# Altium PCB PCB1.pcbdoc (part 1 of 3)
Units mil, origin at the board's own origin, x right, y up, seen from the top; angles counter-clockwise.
Board outline 3256.12 x 1802.31 mil, 4 copper layers (Top Layer, Inner1, Inner2, Bottom Layer); 101 components, 70 nets, 295 pads, 151 vias.
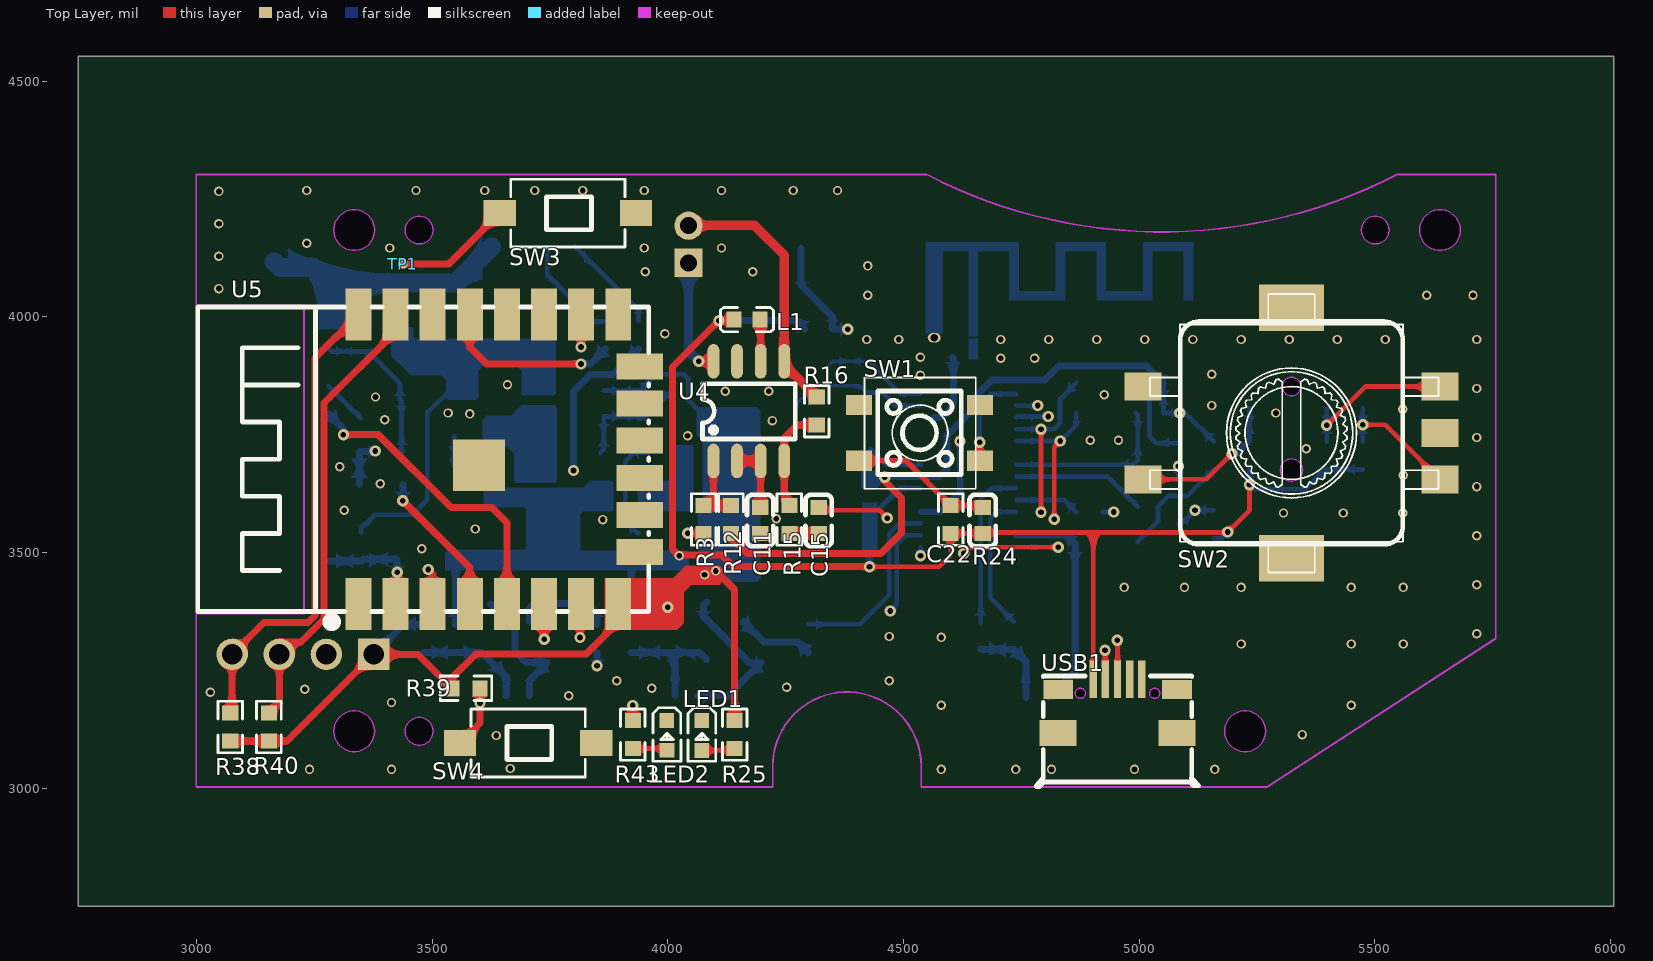
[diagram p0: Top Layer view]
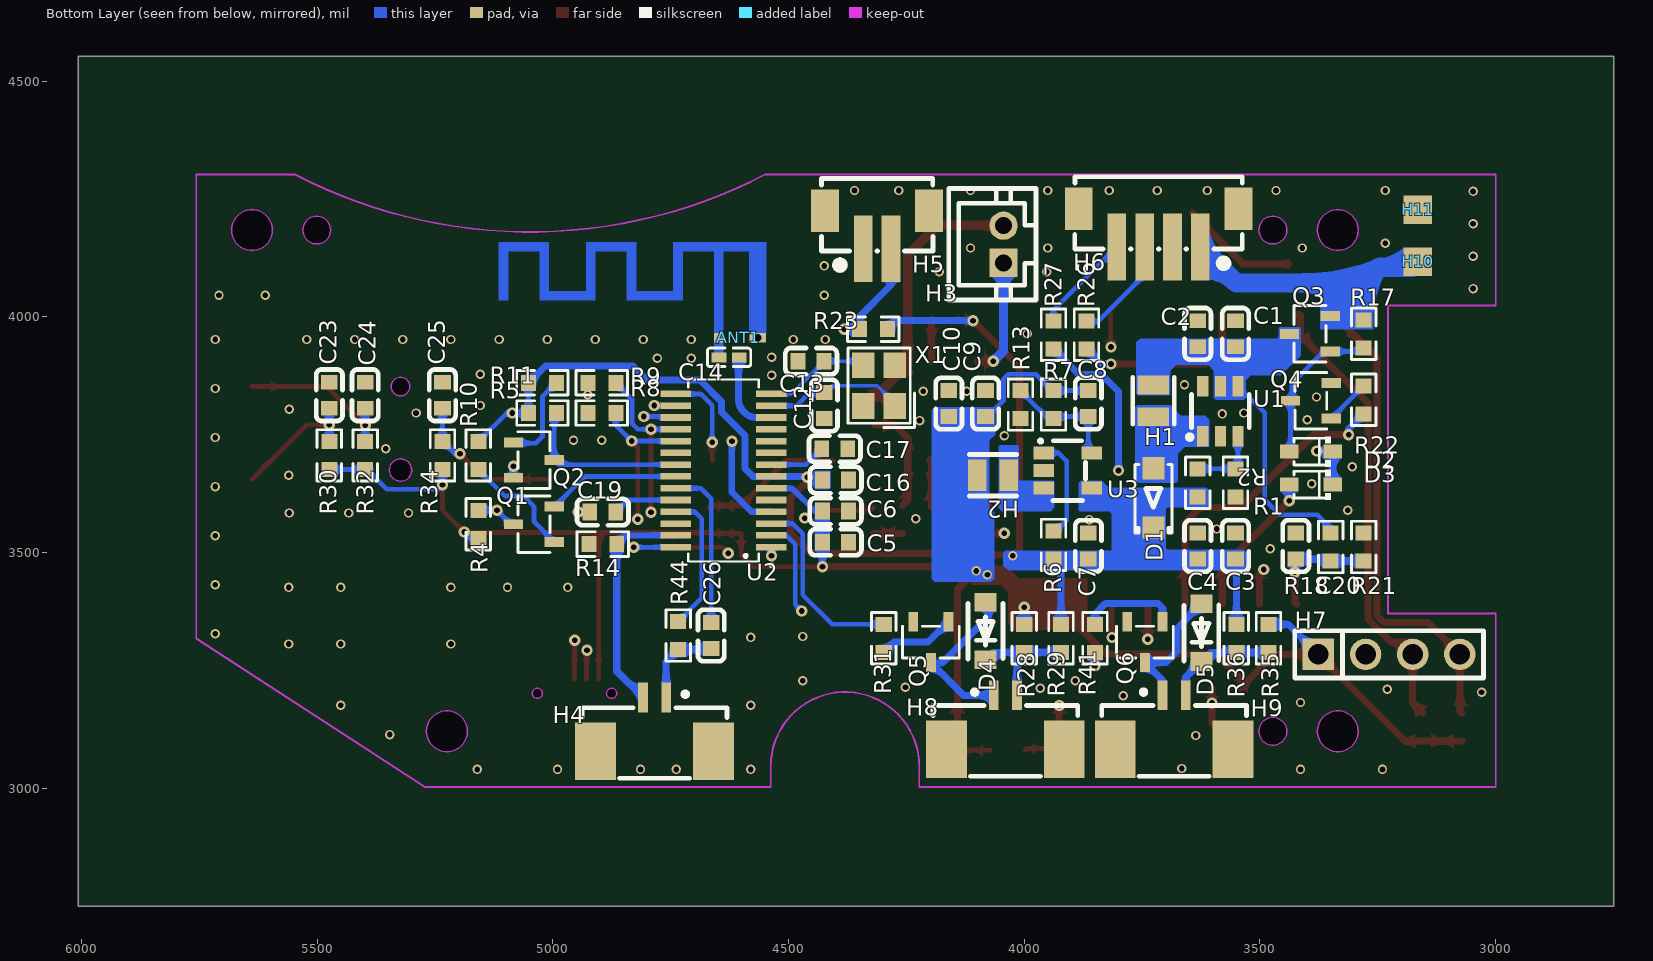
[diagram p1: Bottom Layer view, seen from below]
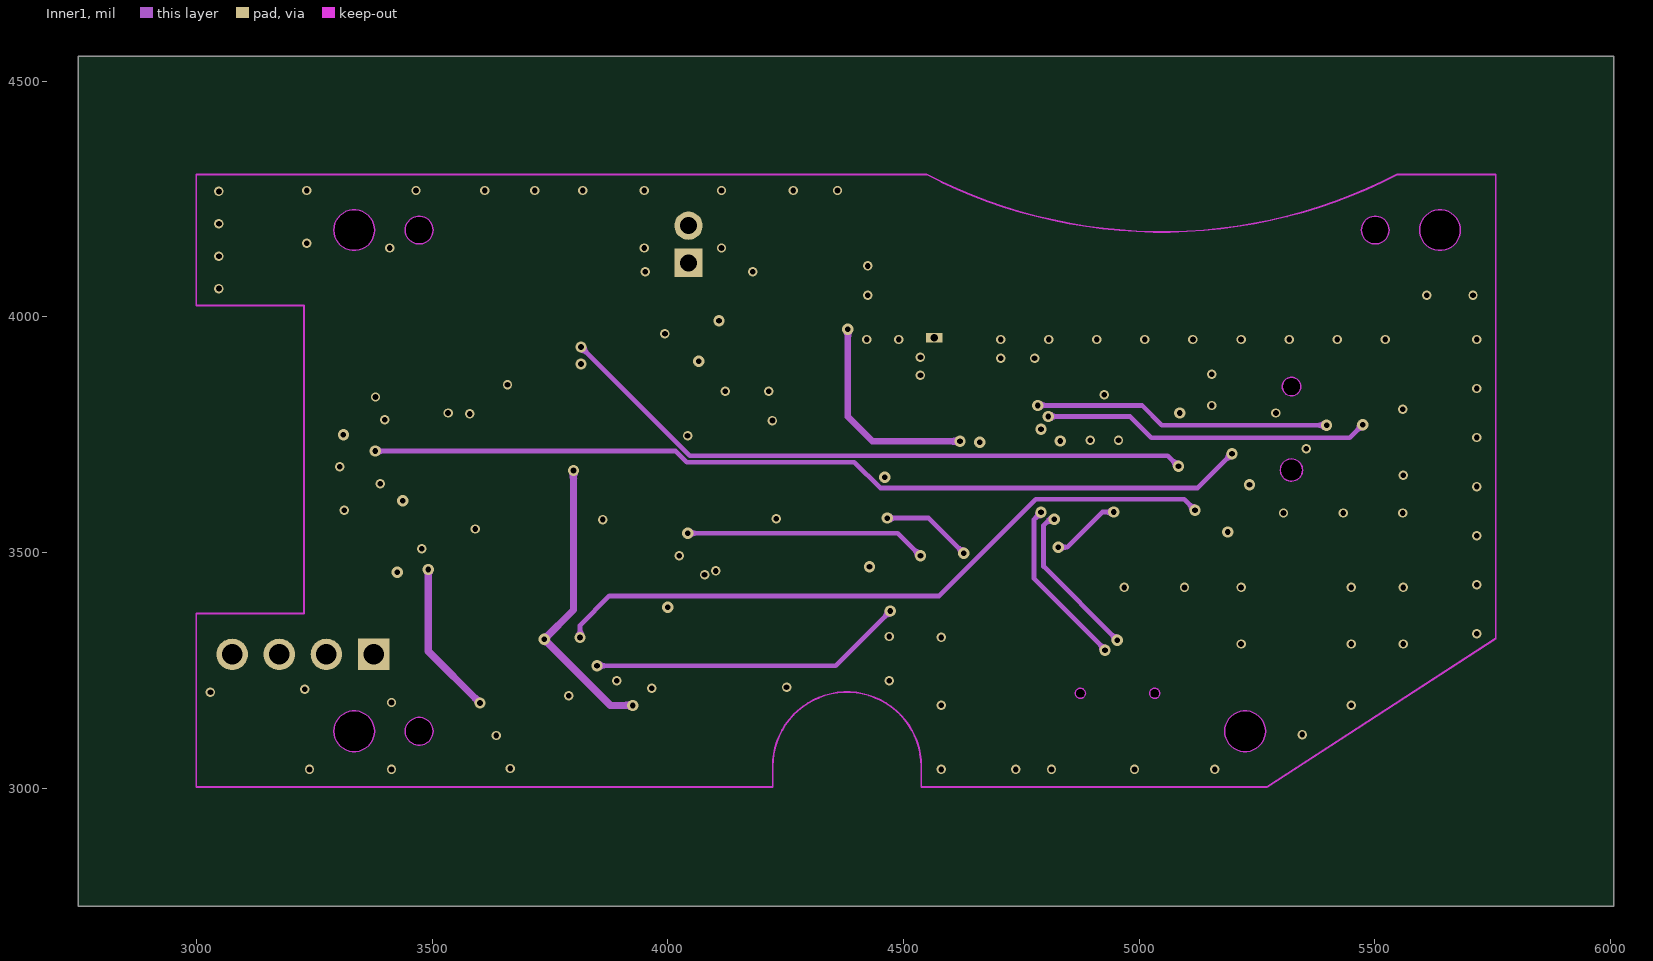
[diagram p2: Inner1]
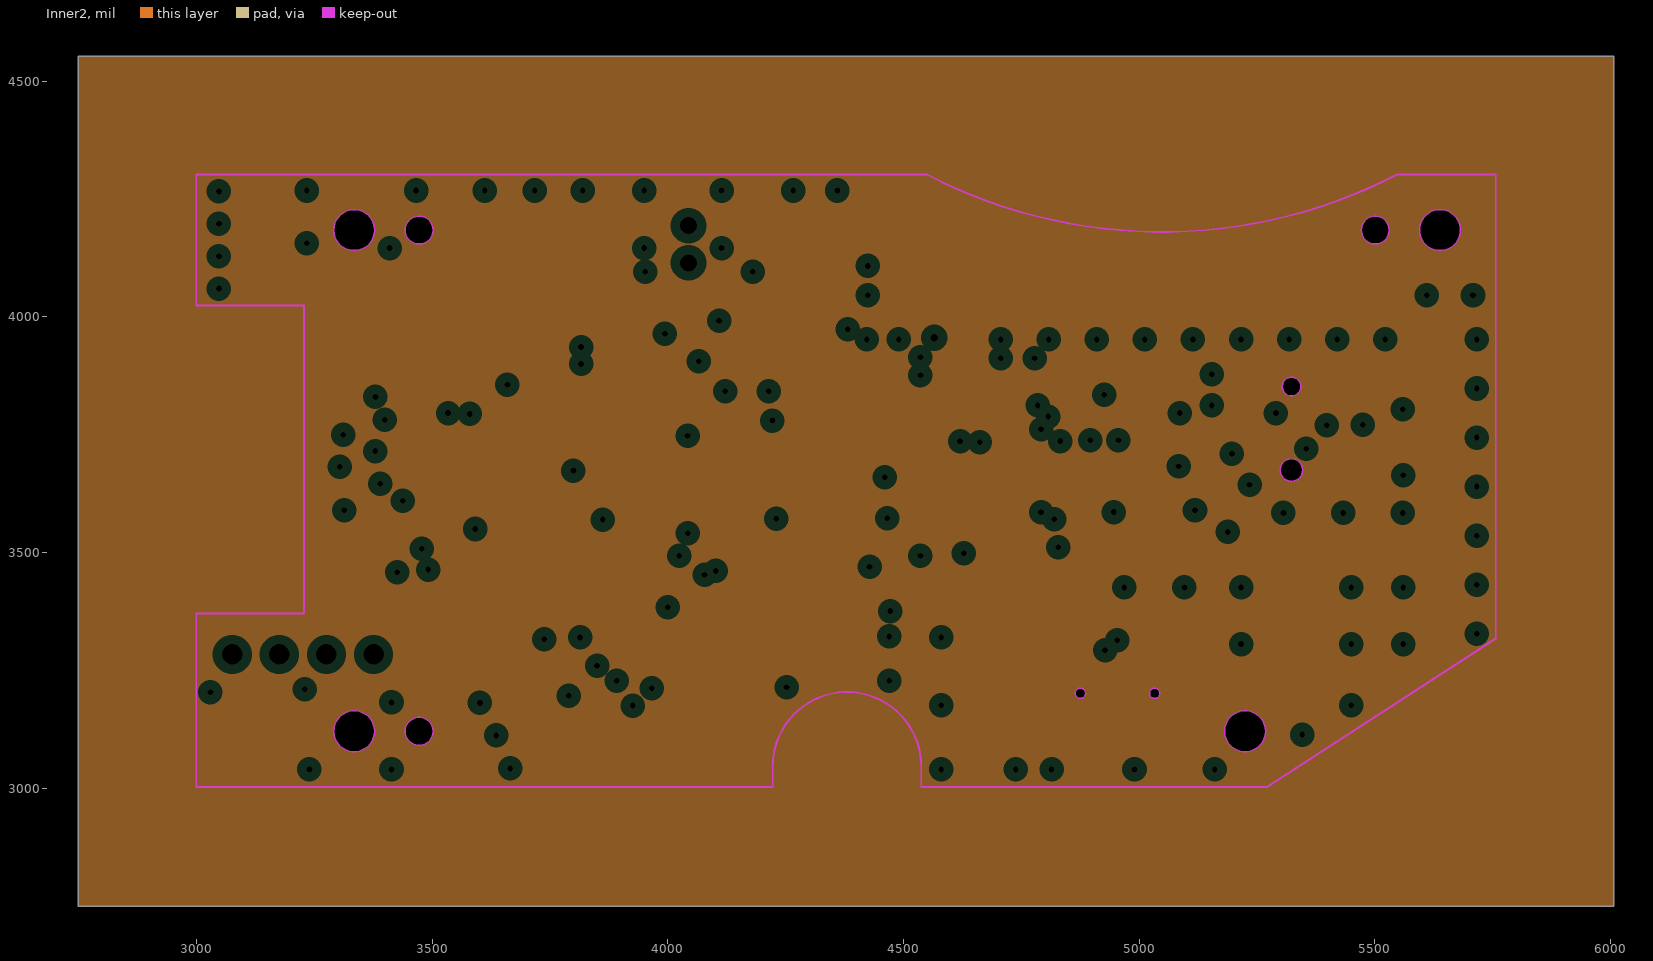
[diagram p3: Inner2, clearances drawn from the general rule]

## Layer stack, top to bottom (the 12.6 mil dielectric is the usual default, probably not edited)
Top Layer: signal copper (thickness not stored)
Dielectric: dielectric 12.6, FR-4, Dk 4.8
Inner1: signal copper (thickness not stored)
Dielectric: dielectric 12.6, FR-4, Dk 4.8
Inner2: plane copper (thickness not stored)
Dielectric: dielectric 12.6, FR-4, Dk 4.8
Bottom Layer: signal copper (thickness not stored)

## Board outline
6006.12,2750 2750,2750 2750,4552.31 6006.12,4552.31
cut-out: 5267.93,3120.93 cw(c5224.62,3120.93) 5181.32,3120.93 cw(c5224.62,3120.93)
cut-out: 5681.32,4183.94 cw(c5638.01,4183.94) 5594.7,4183.94 cw(c5638.01,4183.94)
cut-out: 3378.17,4183.94 cw(c3334.86,4183.94) 3291.55,4183.94 cw(c3334.86,4183.94)
cut-out: 3502.18,3120.93 cw(c3472.66,3120.93) 3443.13,3120.93 cw(c3472.66,3120.93)
cut-out: 3378.17,3120.93 cw(c3334.86,3120.93) 3291.55,3120.93 cw(c3334.86,3120.93)
cut-out: 3443.13,4183.94 cw(c3472.66,4183.94) 3502.18,4183.94 cw(c3472.66,4183.94)
cut-out: 5471.13,4183.94 cw(c5500.66,4183.94) 5530.18,4183.94 cw(c5500.66,4183.94)

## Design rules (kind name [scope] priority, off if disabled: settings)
BoardOutlineClearance copperThickness1oz [All] p0: genericclearance=10 ignorepadtopadclearanceinfootprint=FALSE except(0: Arc-SplitContinuation Track-SplitContinuation SMDPad-SplitContinuation THPad-SplitContinuation Via-SplitContinuation Fill-SplitContinuation Poly-SplitContinuation Region-SplitContinuation Text-SplitContinuation; 6: SMDPad-CutoutEdge THPad-CutoutEdge Via-CutoutEdge Fill-CutoutEdge Region-CutoutEdge; 11.8: Track-OutlineEdge SMDPad-OutlineEdge THPad-OutlineEdge Via-OutlineEdge Fill-OutlineEdge Region-OutlineEdge Poly-OutlineEdge Text-OutlineEdge Track-CutoutEdge)
BoardOutlineClearance copperThickness2oz [All] p0: genericclearance=10 ignorepadtopadclearanceinfootprint=FALSE except(0: Arc-SplitContinuation Track-SplitContinuation SMDPad-SplitContinuation THPad-SplitContinuation Via-SplitContinuation Fill-SplitContinuation Poly-SplitContinuation Region-SplitContinuation Text-SplitContinuation; 6: SMDPad-CutoutEdge THPad-CutoutEdge Via-CutoutEdge Fill-CutoutEdge Region-CutoutEdge; 11.8: Track-OutlineEdge SMDPad-OutlineEdge THPad-OutlineEdge Via-OutlineEdge Fill-OutlineEdge Region-OutlineEdge Poly-OutlineEdge Text-OutlineEdge Track-CutoutEdge)
BoardOutlineClearance copperThicknessInner0.5oz [All] p0: genericclearance=10 ignorepadtopadclearanceinfootprint=FALSE except(0: Arc-SplitContinuation Track-SplitContinuation SMDPad-SplitContinuation THPad-SplitContinuation Via-SplitContinuation Fill-SplitContinuation Poly-SplitContinuation Region-SplitContinuation Text-SplitContinuation; 6: SMDPad-CutoutEdge THPad-CutoutEdge Via-CutoutEdge Fill-CutoutEdge Region-CutoutEdge; 11.8: Track-OutlineEdge SMDPad-OutlineEdge THPad-OutlineEdge Via-OutlineEdge Fill-OutlineEdge Region-OutlineEdge Poly-OutlineEdge Text-OutlineEdge Track-CutoutEdge)
Clearance copperThickness1oz [(InNet('$1N4815') OR InNet('GND') OR InNet('+5V') OR InNet('VCC') OR InNet('$1N2017') OR InNet('VIN') OR InNet('$1N2789') OR InNet('$1N2785') OR InNet('VDDIO') OR InNet('$1N2965') OR InNet('$1N4810') OR InNet('SGND') OR InNet('PC6') OR InNet('$1N5780') OR InNet('$1N6443') OR InNet('DACL') OR InNet('$1N6492') OR InNet('PA0') OR InNet('EC11_A') OR InNet('EC11_B') OR InNet('EC11_D') OR InNet('POWER_ADC') OR InNet('$1N8684') OR InNet('$1N8688') OR InNet('$1N9109') OR InNet('$1N9106') OR InNet('$1N1680') OR InNet('$1N10424') OR InNet('POWER_SW') OR InNet('$1N2005') OR InNet('LOG_TXD') OR InNet('LOG_RXD') OR InNet('$1N6556') OR InNet('$1N8074') OR InNet('$1N8184') OR InNet('$1N5279') OR InNet('PA2') OR InNet('TXD') OR InNet('$1N5314') OR InNet('RXD') OR InNet('PA3') OR InNet('$1N8729') OR InNet('$1N9116') OR InNet('B+') OR InNet('$1N10478') OR InNet('$1N1955') OR InNet('$1N1696') OR InNet('USB_DP') OR InNet('USB_DM') OR InNet('PC7') OR InNet('$1N6373') OR InNet('DACR') OR InNet('$1N6486') OR InNet('SPK-') OR InNet('BOOT') OR InNet('SPK_LED') OR InNet('MUSIC_SW') OR InNet('LED_PWM') OR InNet('MOTOR_PWM') OR InNet('EN') OR InNet('POWER_IO') OR InNet('POWER_LED') OR InNet('$1N10993') OR InNet('$1N10998') OR InNet('PA4') OR InNet('SPK+') OR InNet('KEY_IO') OR InNet('PA1') OR InNet('$1N14735') OR InNet('$1N10634'))] p1: gap=7 ignorepadtopadclearanceinfootprint=FALSE except(4: Track-Track; 6: Track-SMDPad SMDPad-SMDPad Track-THPad SMDPad-THPad THPad-THPad Track-Via SMDPad-Via THPad-Via Via-Via Track-Fill SMDPad-Fill THPad-Fill Via-Fill Fill-Fill SMDPad-Region THPad-Region Via-Region Fill-Region Region-Region Track-Poly SMDPad-Poly THPad-Poly Via-Poly Fill-Poly Poly-Poly Track-Text SMDPad-Text THPad-Text Via-Text Fill-Text Region-Text Poly-Text Text-Text; 6.9: Track-Hole SMDPad-Hole THPad-Hole Via-Hole Fill-Hole Region-Hole Poly-Hole Text-Hole Sheet-Hole; 11.8: Track-Region Region-Poly Track-Sheet SMDPad-Sheet THPad-Sheet Via-Sheet Fill-Sheet Region-Sheet Poly-Sheet Text-Sheet)
Clearance copperThickness2oz [All] p1: gap=7 ignorepadtopadclearanceinfootprint=FALSE except(6: Track-SMDPad SMDPad-SMDPad Track-THPad SMDPad-THPad THPad-THPad Track-Via SMDPad-Via THPad-Via Via-Via Track-Fill SMDPad-Fill THPad-Fill Via-Fill Fill-Fill SMDPad-Region THPad-Region Via-Region Fill-Region Region-Region Track-Poly SMDPad-Poly THPad-Poly Via-Poly Fill-Poly Poly-Poly Track-Text SMDPad-Text THPad-Text Via-Text Fill-Text Region-Text Poly-Text Text-Text; 6.9: Track-Hole SMDPad-Hole THPad-Hole Via-Hole Fill-Hole Region-Hole Poly-Hole Text-Hole Sheet-Hole; 8: Track-Track; 11.8: Track-Region Region-Poly Track-Sheet SMDPad-Sheet THPad-Sheet Via-Sheet Fill-Sheet Region-Sheet Poly-Sheet Text-Sheet)
Clearance copperThicknessInner0.5oz [All] p1: gap=7 ignorepadtopadclearanceinfootprint=FALSE except(3.5: Track-Track; 6: Track-SMDPad SMDPad-SMDPad Track-THPad SMDPad-THPad THPad-THPad Track-Via SMDPad-Via THPad-Via Via-Via Track-Fill SMDPad-Fill THPad-Fill Via-Fill Fill-Fill SMDPad-Region THPad-Region Via-Region Fill-Region Region-Region Track-Poly SMDPad-Poly THPad-Poly Via-Poly Fill-Poly Poly-Poly Track-Text SMDPad-Text THPad-Text Via-Text Fill-Text Region-Text Poly-Text Text-Text; 6.9: Track-Hole SMDPad-Hole THPad-Hole Via-Hole Fill-Hole Region-Hole Poly-Hole Text-Hole Sheet-Hole; 11.8: Track-Region Region-Poly Track-Sheet SMDPad-Sheet THPad-Sheet Via-Sheet Fill-Sheet Region-Sheet Poly-Sheet Text-Sheet)
DiffPairsRouting differentialPair [All] p1: maxuncoupledlength=10 minlimit=5.9843 maxlimit=5.9843 mostfreqgap=5.9843 toplayer_minwidth=5 toplayer_prefwidth=10 toplayer_maxwidth=100 bottomlayer_minwidth=5 bottomlayer_prefwidth=10 bottomlayer_maxwidth=100 midlayer1_minwidth=5 midlayer1_prefwidth=10 midlayer1_maxwidth=100
PasteMaskExpansion pasteMaskExpansion [All] p1: expansion=0
PlaneConnect innerPlane [All] p1: planeconnectstyle=Relief reliefexpansion=20 reliefentries=4 reliefconductorwidth=10 reliefairgap=10
PolygonConnect copperRegion [All] p1: connectstyle=Direct reliefentries=4 reliefconductorwidth=10 polygonreliefangle="90 Angle" airgapwidth=10
RoutingVias viaSize [All] p1: viastyle="Through Hole" holewidth=12.0078 minholewidth=7.874 maxholewidth=248.0316 width=24.0158 minwidth=11.811 maxwidth=393.7008
SolderMaskExpansion solderMaskExpansion [All] p1: useseparateexpansions=TRUE expansion=2.0079 expansionbottom=2.0079
Width copperThickness1oz [All] p1: maxlimit=100 minlimit=4 preferedwidth=10
Width copperThickness2oz [All] p1: maxlimit=100 minlimit=8 preferedwidth=10
Width copperThickness0.5oz [All] p1: maxlimit=100 minlimit=4 preferedwidth=10

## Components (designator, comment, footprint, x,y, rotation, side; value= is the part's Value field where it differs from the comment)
ANT1 "IFA_RF" 板载天线 4898.01,4102 r180 bottom
C1 "CL10A226MQ8NRNC" C0603 3552.01,3964 r270 bottom
C2 "CC0603KRX7R9BB104" C0603 3632.01,3964 r270 bottom
C3 "CL10A226MQ8NRNC" C0603 3552.01,3514 r270 bottom
C4 "CC0603KRX7R9BB104" C0603 3632.01,3514 r270 bottom
C5 "CL10A105KB8NNNC" C0603 4400,3522 r0 bottom
C6 "CC0603KRX7R9BB104" C0603 4400.01,3588 r0 bottom
C7 "CL10A106KP8NNNC" C0603 3864,3514 r90 bottom
C8 "CL10C220JB8NNNC" C0603 3864.01,3816 r90 bottom
C9 "CL10A106KP8NNNC" C0603 4082.06,3816 r270 bottom
C10 "CC0603KRX7R9BB104" C0603 4160.01,3816 r270 bottom
C11 "CL10A105KB8NNNC" C0603 4196.01,3568 r90 top
C12 "0603CG240J500NT" C0603 4424.01,3812 r90 bottom
C13 "0603CG240J500NT" C0603 4452.01,3906 r0 bottom
C14 "0402CG2R7C500NT" C0402 4626.01,3914 r180 bottom
C15 "CC0603KRX7R9BB104" C0603 4320.01,3568 r90 top
C16 "CL10A105KB8NNNC" C0603 4400.01,3654 r0 bottom
C17 "CL10A105KB8NNNC" C0603 4402.01,3720 r0 bottom
C19 "CL10A105KB8NNNC" C0603 4894.01,3586 r0 bottom
C20 "CC0603KRX7R9BB104" C0603 3424.01,3514 r270 bottom
C22 "CC0603KRX7R9BB104" C0603 4668.01,3568 r90 top
C23 "CC0603KRX7R9BB104" C0603 5473.95,3833.81 r90 bottom
C24 "CC0603KRX7R9BB104" C0603 5398.06,3833.81 r90 bottom
C25 "CC0603KRX7R9BB104" C0603 5234.06,3833.81 r90 bottom
C26 "CL10A105KB8NNNC" C0603 4664.01,3324 r90 bottom
D1 "SS14_C2909920" SOD-123FL_L2.8-W1.8-LS3.7-RD 3726.01,3616 r90 bottom
D2 "1N4148WS_C2128" SOD-323_L1.8-W1.3-LS2.5-RD 3392.01,3714 r0 bottom
D3 "1N4148WS_C2128" SOD-323_L1.8-W1.3-LS2.5-RD 3392.01,3644 r0 bottom
D4 "SM4007PL_C64898" SOD-123F_L2.8-W1.8-LS3.7-RD 4082.01,3334 r90 bottom
D5 "SM4007PL_C64898" SOD-123F_L2.8-W1.8-LS3.7-RD 3624.01,3330 r90 bottom
H1 "FTC201610S2R2MBCA" IND-SMD_L2.0-W1.6-B 3726.01,3822 r270 bottom
H2 "FTC201610S2R2MBCA" IND-SMD_L2.0-W1.6-B 4066.01,3664 r0 bottom
H3 "JS20T-S02PHA-00" CONN-TH_2P-P2.00_JS20T-S02PHA-00 4044.01,4154 r90 bottom
H4 "1.25-2P" CONN-SMD_1.25-2P#1 4784.09,3135.56 r180 bottom
H5 "ZX-ZH1.5-2PLT" CONN-SMD_2P-P1.50_ZX-ZH1.5-2PLT 4312.12,4184.81 r180 bottom
H6 "ZX-ZH1.5-4PLT" CONN-SMD_4P-P1.50_ZX-ZH1.5-4PLT 3715,4188.72 r180 bottom locked
H7 "PZ254V-11-04P" HDR-TH_4P-P2.54-V-M 3226.01,3284 r180 bottom
H8 "1.25-2P" CONN-SMD_1.25-2P#2 4040.01,3140 r180 bottom
H9 "1.25-2P" CONN-SMD_1.25-2P#2 3682.01,3140 r180 bottom
H10 "标志位" 标志点 2460.01,3662 r180 bottom
H11 "标志位" 标志点 2460.01,3772 r180 bottom
L1 "PZ1608D600-2R0TF" L0603 4168.01,3994 r180 top
LED1 "KT-0603R" LED0603-RD 4072.01,3112 r270 top
LED2 "XL-1608UBC-04" LED0603-RD_BLUE 3998.01,3112 r270 top
Q1 "S8050_C364312" SOT-23-3_L3.0-W1.7-P0.95-LS2.9-BR 5040.01,3560 r180 bottom
Q2 "S8050_C364312" SOT-23-3_L3.0-W1.7-P0.95-LS2.9-BR 5040.01,3696 r0 bottom
Q3 "AO3415A_C347479" SOT-23-3_L3.0-W1.7-P0.95-LS2.9-BR 3394.01,3964 r180 bottom
Q4 "AO3416A" SOT-23-3_L3.0-W1.7-P0.95-LS2.9-BR 3392.01,3822 r180 bottom
Q5 "S8050 J3Y(RANGE:200-350)" SOT-23-3_L3.0-W1.7-P0.95-LS2.9-BR 4198.01,3310 r90 bottom
Q6 "S8050 J3Y(RANGE:200-350)" SOT-23-3_L3.0-W1.7-P0.95-LS2.9-BR 3744.01,3310 r90 bottom
R1 "0603WAF1103T5E" R0603 3632.01,3648 r270 bottom
R2 "0603WAF1502T5E" R0603 3552.01,3648 r270 bottom
R3 "0603WAF1001T5E" R0603 4076.01,3570.19 r90 top
R4 "0603WAF1002T5E" R0603 5158.01,3560 r90 bottom
R5 "0603WAF1002T5E" R0603 5022.01,3796 r180 bottom
R6 "0603WAF1002T5E" R0603 3938.01,3516.19 r90 bottom
R7 "0603WAF6802T5E" R0603 3938.01,3813.81 r90 bottom
R8 "0603WAF1002T5E" R0603 4896.01,3796 r0 bottom
R9 "0603WAF1002T5E" R0603 4896.01,3860 r0 bottom
R10 "0603WAF4701T5E" R0603 5158.01,3706 r270 bottom
R11 "0603WAF4701T5E" R0603 5022.01,3860 r180 bottom
R12 "0603WAF1002T5E" R0603 4134.01,3570.19 r90 top
R13 "0603WAF1502T5E" R0603 4008.06,3813.81 r90 bottom
R14 "0603WAF0000T5E" R0603 4894.01,3518 r180 bottom
R15 "0603WAF4701T5E" R0603 4258.01,3570.19 r90 top
R16 "0603WAF2702T5E" R0603 4316.01,3800 r90 top
R17 "0603WAF5102T5E" R0603 3280.01,3964 r90 bottom
R18 "0603WAF1003T5E" R0603 3350.01,3511.81 r90 bottom
R21 "0603WAF1003T5E" R0603 3280.01,3511.81 r270 bottom
R22 "0603WAF1001T5E" R0603 3280.01,3824 r270 bottom
R23 "0603WAF1002T5E" R0603 4320.01,3974 r180 bottom
R24 "0603WAF4701T5E" R0603 4600.01,3570.19 r270 top
R25 "0603WAF1002T5E" R0603 4142.01,3114 r90 top
R26 "0603WAF0000T5E" R0603 3867.95,3961.81 r270 bottom
R27 "0603WAF0000T5E" R0603 3938.01,3961.81 r270 bottom
R28 "0603WAF0000T5E" R0603 4000.01,3318 r90 bottom
R29 "0603WAF0000T5E" R0603 3922.01,3318 r90 bottom
R30 "0603WAF4701T5E" R0603 5474.01,3706 r270 bottom
R31 "0603WAF1001T5E" R0603 4298.01,3318 r270 bottom
R32 "0603WAF4701T5E" R0603 5398.01,3706 r270 bottom
R34 "0603WAF4701T5E" R0603 5234.01,3706 r270 bottom
R35 "0603WAF0000T5E" R0603 3482.01,3318 r90 bottom
R36 "0603WAF0000T5E" R0603 3550.01,3318 r90 bottom
R38 "0603WAF4701T5E" R0603 3072.01,3130 r270 top
R39 "0603WAF4701T5E" R0603 3572.01,3212 r180 top
R40 "0603WAF4701T5E" R0603 3154.01,3130 r270 top
R41 "0603WAF1001T5E" R0603 3850.01,3318 r90 bottom
R43 "0603WAF1002T5E" R0603 3926.01,3114 r90 top
R44 "0603WAF2201T5E" R0603 4734.01,3324 r270 bottom
SW1 "YZA-056-5.0" SW-SMD_4P-L4.5-W4.5-P3.00-LS6.8 4534.01,3754 r0 top
SW2 "EC11J1525402" EC11 5323.01,3753.7 r90 top
SW3 "TSB008A2530A" SW-SMD_L6.0-W3.5-LS8.0 3788.01,4220 r0 top
SW4 "TSB008A2530A" SW-SMD_L6.0-W3.5-LS8.0 3704.01,3096 r0 top
TP1 "Test-Point" Test-Point-0.5mm 3438.01,4112 r0 top
U1 "STI3508C" SOT-23-6_L2.9-W1.6-P0.95-LS2.8-BR 3584.01,3800 r270 bottom
U2 "YT2228" QSOP-28_L9.9-W3.9-P0.64-LS6.0-BL 4638.01,3674 r90 bottom
U3 "RT8059GJ5-TP" SOT-23-5_L2.9-W1.6-P0.95-LS2.8-BR_1 3908.01,3674 r0 bottom
U4 "8002A" SOP-8_L4.9-W3.9-P1.27-LS6.0-BL 4172.01,3800 r0 top
U5 "Ai-WB2-12F" COMM-SMD_22P-L24.0-W16.0-P2.00_ZIGBEE 3642.01,3698 r90 top
USB1 "MicroQTJ" MICRO-USB-SMD_MICROQTJ-5P 4954.01,3174 r0 top
X1 "X322524MOB4SI" CRYSTAL-SMD_4P-L3.2-W2.5-BL 4308.01,3854 r90 bottom

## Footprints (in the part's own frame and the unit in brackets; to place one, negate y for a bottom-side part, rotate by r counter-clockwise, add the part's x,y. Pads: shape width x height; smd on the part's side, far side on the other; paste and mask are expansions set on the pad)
C0402 [mm]
  rect 0.79x0.54 smd: 1(-0.545,0) 2(0.545,0)
  silkscreen extent -1.17,-0.5 1.17,0.5
C0603 [mm]
  rect 0.8x0.9 smd: 1(-0.7,0) 2(0.7,0)
  silkscreen extent -1.39,-0.71 1.39,0.71
COMM-SMD_22P-L24.0-W16.0-P2.00_ZIGBEE [mm]
  rect 2.8x1.4 smd: 1(-7.8,7.575) 2(-7.8,5.575) 3(-7.8,3.575) 4(-7.8,1.575) 5(-7.8,-0.425) 6(-7.8,-2.425) 7(-7.8,-4.425) 8(-7.8,-6.425) 9(7.8,-6.425) 10(7.8,-4.425) 11(7.8,-2.425) 12(7.8,-0.425) 13(7.8,1.575) 14(7.8,3.575) 15(7.8,5.575) 16(7.8,7.575)
  rect 1.4x2.5 smd: 17(-5,-7.575) 18(-3,-7.575) 19(-1,-7.575) 20(1,-7.575) 21(3,-7.575) 22(5,-7.575)
  rect 2.8x2.8 smd: 23(-0.325,1.075)
  silkscreen extent -9.01,-8.08 8.2,16.23
CONN-SMD_1.25-2P#1 [mm]
  rect 0.52x1.6 smd: 1(0.625,1.45) 2(-0.625,1.45)
  rect 2.2x3.1 smd: 3(-3.175,-1.45) 4(3.175,-1.45)
  silkscreen extent -3.9,-2.9 3.9,1.75
CONN-SMD_1.25-2P#2 [mm]
  rect 0.52x1.6 smd: 1(-0.625,1.45) 2(0.625,1.45)
  rect 2.2x3.1 smd: 3(3.175,-1.45) 4(-3.175,-1.45)
  silkscreen extent -3.9,-2.9 3.9,1.75
CONN-SMD_2P-P1.50_ZX-ZH1.5-2PLT [mm]
  rect 1x3.6 smd: 1(-0.75,-1.025) 2(0.75,-1.025)
  rect 1.5x2.3 smd: 3(2.8,1.025) 4(-2.8,1.025)
  silkscreen extent -3,-2.31 3.02,2.76
CONN-SMD_4P-P1.50_ZX-ZH1.5-4PLT [mm]
  rect 1x3.6 smd: 1(2.25,-1.025) 2(0.75,-1.025) 3(-0.75,-1.025) 4(-2.25,-1.025)
  rect 1.5x2.3 smd: 5(-4.3,1.025) 6(4.3,1.025)
  silkscreen extent -4.52,-2.31 4.5,2.76
CONN-TH_2P-P2.00_JS20T-S02PHA-00 [mil]
  rect 60x60 hole 36: 1(-39.37,0)
  round 60 hole 36: 2(39.37,0)
  silkscreen extent -118,-69 118,116
CRYSTAL-SMD_4P-L3.2-W2.5-BL [mm]
  rect 1.4x1.2 smd: 1(-1.1,-0.85) 2(1.1,-0.85) 3(1.1,0.85) 4(-1.1,0.85)
  silkscreen extent -2.26,-1.91 2.03,1.68
EC11 [mm]
  rect 1.5x2 smd: A(-2.5,-8) B(2.5,-8) C(0,-8) D(-2.5,8) E(2.5,8)
  rect 2.5x3.5 smd: ""(-6.75,0) ""(6.75,0)
  Board Outline Layer circle w0.025: c-2,0 r0.6
  Board Outline Layer circle w0.025: c2.5,0 r0.5
  Board Outline Layer region: -2,-0.6 -2.26,-0.541 -2.469,-0.374 -2.585,-0.134 -2.585,0.134 -2.469,0.374 -2.26,0.541 -2,0.6 -2,0.6 -1.74,0.541 -1.531,0.374 -1.415,0.134 -1.415,-0.134 -1.531,-0.374 -1.74,-0.541 -2,-0.6
  Board Outline Layer region: 2.5,-0.5 2.283,-0.45 2.109,-0.312 2.013,-0.111 2.013,0.111 2.109,0.312 2.283,0.45 2.5,0.5 2.5,0.5 2.717,0.45 2.891,0.312 2.987,0.111 2.987,-0.111 2.891,-0.312 2.717,-0.45 2.5,-0.5
  Multi-Layer board cut-out: -2,-0.6 -2.26,-0.541 -2.469,-0.374 -2.585,-0.134 -2.585,0.134 -2.469,0.374 -2.26,0.541 -2,0.6 -2,0.6 -1.74,0.541 -1.531,0.374 -1.415,0.134 -1.415,-0.134 -1.531,-0.374 -1.74,-0.541 -2,-0.6
  Multi-Layer board cut-out: 2.5,-0.5 2.283,-0.45 2.109,-0.312 2.013,-0.111 2.013,0.111 2.109,0.312 2.283,0.45 2.5,0.5 2.5,0.5 2.717,0.45 2.891,0.312 2.987,0.111 2.987,-0.111 2.891,-0.312 2.717,-0.45 2.5,-0.5
  silkscreen extent -6,-6 6,6
HDR-TH_4P-P2.54-V-M [mm]
  rect 1.7x1.7 hole 1.1: 1(-3.81,0)
  round 1.7 hole 1.1: 2(-1.27,0) 3(1.27,0) 4(3.81,0)
  silkscreen extent -5.08,-1.27 5.08,1.27
IND-SMD_L2.0-W1.6-B [mm]
  rect 1x1.7 smd: 1(-0.85,0) 2(0.85,0)
  silkscreen extent -1.27,-1.12 1.27,1.12
L0603 [mm]
  rect 0.8x0.864 smd: 1(-0.7,0) 2(0.7,0)
  silkscreen extent -1.42,-0.65 1.42,0.65
LED0603-RD [mm]
  rect 0.8x0.8 smd: 1(-0.799,0) 2(0.799,0)
  silkscreen extent -1.49,-0.75 1.39,0.76
LED0603-RD_BLUE [mm]
  rect 0.8x0.8 smd: 1(-0.8,-0.004) 2(0.799,0.004)
  silkscreen extent -1.49,-0.75 1.39,0.76
MICRO-USB-SMD_MICROQTJ-5P [mm]
  rect 0.4x2 smd: 1(-1.3,1.452) 2(-0.65,1.452) 3(0,1.452) 4(0.65,1.452) 5(1.3,1.452)
  rect 1.6x1 smd: 6(-3.2,0.902) 9(3.2,0.902)
  rect 2x1.4 smd: 7(-3.2,-1.452) 8(3.2,-1.452)
  Board Outline Layer circle w0.005: c2,0.698 r0.275
  Board Outline Layer circle w0.005: c-2,0.698 r0.275
  Board Outline Layer region: 2.275,0.698 2.248,0.579 2.171,0.483 2.061,0.43 1.939,0.43 1.828,0.483 1.752,0.579 1.725,0.698 1.725,0.698 1.752,0.817 1.828,0.913 1.939,0.966 2.061,0.966 2.171,0.913 2.248,0.817 2.275,0.698
  Board Outline Layer region: -1.725,0.698 -1.752,0.579 -1.829,0.483 -1.939,0.43 -2.061,0.43 -2.172,0.483 -2.248,0.579 -2.275,0.698 -2.275,0.698 -2.248,0.817 -2.172,0.913 -2.061,0.966 -1.939,0.966 -1.829,0.913 -1.752,0.817 -1.725,0.698
  Multi-Layer board cut-out: 2.275,0.698 2.248,0.579 2.171,0.483 2.061,0.43 1.939,0.43 1.828,0.483 1.752,0.579 1.725,0.698 1.725,0.698 1.752,0.817 1.828,0.913 1.939,0.966 2.061,0.966 2.171,0.913 2.248,0.817 2.275,0.698
  Multi-Layer board cut-out: -1.725,0.698 -1.752,0.579 -1.829,0.483 -1.939,0.43 -2.061,0.43 -2.172,0.483 -2.248,0.579 -2.275,0.698 -2.275,0.698 -2.248,0.817 -2.172,0.913 -2.061,0.966 -1.939,0.966 -1.829,0.913 -1.752,0.817 -1.725,0.698
  silkscreen extent -4.37,-4.34 4.38,1.63
QSOP-28_L9.9-W3.9-P0.64-LS6.0-BL [mil]
  rect 14x64.57 smd: 1(-162.5,-101.18) 2(-137.5,-101.18) 3(-112.5,-101.18) 4(-87.5,-101.18) 5(-62.5,-101.18) 6(-37.5,-101.18) 7(-12.5,-101.18) 8(12.5,-101.18) 9(37.5,-101.18) 10(62.5,-101.18) 11(87.5,-101.18) 12(112.5,-101.18) 13(137.5,-101.18) 14(162.5,-101.18) 15(162.5,101.18) 16(137.5,101.18) 17(112.5,101.18) 18(87.5,101.18) 19(62.5,101.18) 20(37.5,101.18) 21(12.5,101.18) 22(-12.5,101.18) 23(-37.5,101.18) 24(-62.5,101.18) 25(-87.5,101.18) 26(-112.5,101.18) 27(-137.5,101.18) 28(-162.5,101.18)
  silkscreen extent -204,-106 193,75
R0603 [mil]
  rect 31.75x34.02 smd: 1(-29.66,0) 2(29.66,0)
  silkscreen extent -55,-26 55,26
SOD-123F_L2.8-W1.8-LS3.7-RD [mm]
  rect 1x1.2 smd: 1(-1.55,0) 2(1.55,0)
  silkscreen extent -1.52,-0.93 1.49,0.95
SOD-123FL_L2.8-W1.8-LS3.7-RD [mm]
  rect 1.2x1.2 smd: 1(-1.6,0) 2(1.6,0)
  silkscreen extent -1.9,-1 1.8,1
SOD-323_L1.8-W1.3-LS2.5-RD [mm]
  rect 1x0.75 smd: 1(-1.173,0) 2(1.173,0)
  silkscreen extent -1.08,-0.8 0.9,0.8
SOP-8_L4.9-W3.9-P1.27-LS6.0-BL [mm]
  oval 0.63x1.865 smd: 1(-1.905,-2.682) 2(-0.635,-2.682) 3(0.635,-2.682) 4(1.905,-2.682) 5(1.905,2.682) 6(0.635,2.682) 7(-0.635,2.682) 8(-1.905,2.682)
  silkscreen extent -2.5,-1.5 2.5,1.48
SOT-23-3_L3.0-W1.7-P0.95-LS2.9-BR [mil]
  rect 40.85x20.95 smd: 1(43.36,-37.4) 2(43.36,37.4) 3(-43.36,0)
  silkscreen extent -34,-60 34,60
SOT-23-5_L2.9-W1.6-P0.95-LS2.8-BR_1 [mm]
  rect 1.1x0.7 smd: 1(1.294,-0.951) 2(1.294,-0.001) 3(1.294,0.951) 4(-1.294,0.951) 5(-1.294,-0.949)
  silkscreen extent -0.97,-1.65 1.52,1.61
SOT-23-6_L2.9-W1.6-P0.95-LS2.8-BR [mm]
  rect 1.1x0.6 smd: 1(1.35,-0.95) 2(1.35,0) 3(1.35,0.95) 4(-1.35,0.95) 5(-1.35,0) 6(-1.35,-0.95)
  silkscreen extent -0.9,-1.78 1.52,1.55
SW-SMD_4P-L4.5-W4.5-P3.00-LS6.8 [mm]
  rect 1.4x1.1 smd: 1(-3.25,1.5) 2(3.25,1.5) 3(-3.25,-1.5) 4(3.25,-1.5)
  silkscreen extent -2.25,-2.25 2.25,2.25
SW-SMD_L6.0-W3.5-LS8.0 [mm]
  rect 1.74x1.4 smd: 1(-3.67,0) 2(3.67,0)
  silkscreen extent -3.08,-1.83 3.08,1.83
Test-Point-0.5mm [mm]
  round 0.5 smd: 1(0,0)
板载天线 [mm]
  rect 0.9x0.5 / inner rect 0.9x0.5 / far side oval 0.7x0.5 hole 0.4: 1(8.453,-3.716)
  rect 0.5x0.5 smd: 2(6.353,-3.716)
  Top Layer region: 6.103,-3.623 6.103,1.184 6.604,1.184 6.604,-3.623
  Top Layer region: 3.902,-1.706 3.902,1.434 4.402,1.434 4.402,-1.706
  Top Layer region: 1.403,-1.706 1.403,1.434 1.904,1.434 1.904,-1.706
  Top Layer region: -3.297,-1.706 -3.297,1.434 -2.797,1.434 -2.797,-1.706
  Top Layer region: -5.497,-1.706 -5.497,1.434 -4.997,1.434 -4.997,-1.706
  Top Layer region: 8.002,-3.481 8.002,1.434 8.901,1.434 8.901,-3.481
  Top Layer region: 1.403,-1.706 1.403,-1.206 4.403,-1.206 4.403,-1.706
  Top Layer region: -0.797,-1.706 -0.797,1.434 -0.297,1.434 -0.297,-1.706
  Top Layer region: -0.797,0.934 -0.797,1.434 1.904,1.434 1.904,0.934
  Top Layer region: -5.497,0.935 -5.497,1.434 -2.797,1.434 -2.797,0.935
  Top Layer region: -3.297,-1.706 -3.297,-1.206 -0.596,-1.206 -0.596,-1.706
  Top Layer region: 3.953,1.434 8.453,1.434 8.453,0.935 3.953,0.935
标志点 [mil]
  rect 60x60 smd: 1(-705,455)

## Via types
v1: diameter 20, hole 12.01, Top Layer to Bottom Layer, 104 vias
v2: diameter 24.02, hole 12.01, Top Layer to Bottom Layer, 44 vias
v3: diameter 20, hole 12, Top Layer to Bottom Layer, 3 vias

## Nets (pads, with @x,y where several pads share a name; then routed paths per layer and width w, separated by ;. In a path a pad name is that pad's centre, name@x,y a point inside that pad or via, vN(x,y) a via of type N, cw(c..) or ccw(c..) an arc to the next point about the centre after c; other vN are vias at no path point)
$1N1680: D1.2 H1.2 U1.1
$1N1696: R1.1 R2.1 U1.3 | length 151.4
  Bottom Layer w10: U1.3@3546.61,3746.85 3546.61,3683.06 R2.1@3552.01,3677.66 R1.1@3632.01,3677.66
$1N1955: R6.2 U3.1 | length 221.2
  Bottom Layer w10: R6.2@3938.01,3541.47 3936.54,3541.47 3910.01,3568 3910.01,3694 3927.45,3711.44 U3.1@3958.95,3711.44
$1N2005: H2.1 U3.3 | length 85
  Bottom Layer w10: U3.3@3958.95,3636.56 4005.1,3636.56 H2.1@4032.54,3664
$1N2017: C8.1 R7.1 R13.2 U3.5 | length 250.4
  Bottom Layer w10: U3.5@3857.06,3711.36 3864.01,3718.3 C8.1@3864.01,3788.44 3933.72,3788.44 R7.1@3938.01,3784.15 3948.74,3784.15 R13.2@4008.06,3843.47
$1N2785: C13.1 U2.14 X1.3 | length 227.7
  Bottom Layer w8: X1.3@4341.47,3897.31 4350.16,3906 C13.1@4424.45,3906 4493.95,3836.5 U2.14@4536.83,3836.5
$1N2789: C12.2 U2.13 X1.1 | length 299.3
  Bottom Layer w8: X1.1@4274.54,3810.69 4274.54,3816.69 4311.85,3854 4407.57,3854 C12.2@4422.01,3839.56
  Bottom Layer w10: C12.2@4424.01,3839.56 4454.45,3839.56 4482.51,3811.5 U2.13@4536.83,3811.5
$1N2965: C17.2 U2.8 | length 121.1
  Bottom Layer w10: C17.2@4429.57,3720 4463.07,3686.5 U2.8@4536.83,3686.5
$1N4810: C14.2 U2.12 | length 151.6
  Bottom Layer w15: U2.12@4566.01,3786 ccw(c4566.19,3825.87) 4606.01,3828 4606.01,3912.54 C14.2@4604.55,3914
$1N4815: ANT1.2 C14.1
$1N5279: Q1.1 R10.2 | length 244
  Bottom Layer w10: Q1.1@4996.65,3522.6 5040.01,3565.96 5040.01,3598 5062.01,3620 5102.01,3620 5158.01,3676 R10.2@5158.01,3676.34
$1N5314: Q2.1 R11.2 | length 194
  Bottom Layer w10: R11.2@4992.35,3860 5022.01,3830.34 5022.01,3746 5036.01,3732 5081.97,3732 Q2.1@5083.37,3733.4
$1N5780: C26.1 H4.1 R44.2 | length 183.1
  Bottom Layer w15: C26.1@4664.01,3296.44 4666.11,3294.34 R44.2@4734.01,3294.34 4759.48,3268.86 H4.1@4759.48,3192.64
$1N6373: R3.2 R12.2 U4.1 | length 161.2
  Top Layer w15: U4.1@4097.01,3694.39 4097.01,3620.85 R3.2@4076.01,3599.85 R12.2@4134.01,3599.85
$1N6443: C11.2 U4.2 U4.3 | length 149.2
  Top Layer w15: C11.2@4196.01,3595.56 4197.01,3596.56 U4.3@4197.01,3694.39
  Top Layer w20: U4.2@4147.01,3694.39 U4.3@4197.01,3694.39
$1N6486: R15.2 R16.1 U4.4 | length 228
  Top Layer w15: R15.2@4258.01,3599.85 4247.01,3610.85 U4.4@4247.01,3694.39 4247.01,3743 4274.35,3770.34 R16.1@4316.01,3770.34
$1N6492: C15.1 R15.1 | length 62
  Top Layer w15: R15.1@4258.01,3540.53 4319.91,3540.53 C15.1@4320.01,3540.44
$1N6556: L1.1 U4.6 | length 89
  Top Layer w15: L1.1@4195.56,3994 4197.01,3992.55 U4.6@4197.01,3905.61
$1N8074: LED1.2 R25.1 | length 71.6
  Top Layer w10: LED1.2@4072.01,3080.53 4138.19,3080.53 R25.1@4142.01,3084.34
$1N8184: LED2.2 R43.1 | length 73.7
  Top Layer w10: R43.1@3926.01,3084.34 3994.33,3084.34 LED2.2@3998.14,3080.53
$1N8684: D4.2 H8.1 Q5.3 | length 348.3
  Bottom Layer w15: H8.1@4064.62,3197.09 4128.45,3197.09 Q5.3@4198.01,3266.64 ; D4.2@4082.01,3395.02 4076.01,3389.02 4076.01,3364 4174.01,3266 Q5.3@4188.01,3266
$1N8688: D4.1 H8.2 R28.1 R29.1 | length 264
  Bottom Layer w15: R29.1@3922.01,3288.34 R28.1@4000.01,3288.34 ; H8.2@4015.4,3197.09 4015.4,3272.95 R28.1@4000.01,3288.34 ; D4.1@4082.01,3272.98 4066.65,3288.34 R28.1@4000.01,3288.34
$1N8729: Q5.1 R31.2 | length 164.3
  Bottom Layer w15: Q5.1@4160.61,3353.36 4203.97,3310 4276.35,3310 R31.2@4298.01,3288.34
$1N9106: D5.1 H9.2 R35.1 R36.1 | length 235.7
  Bottom Layer w15: R35.1@3482.01,3288.34 R36.1@3550.01,3288.34 3604.65,3288.34 D5.1@3624.01,3268.98 3657.4,3235.59 H9.2@3657.4,3197.09
$1N9109: D5.2 H9.1 Q6.3 | length 285.3
  Bottom Layer w15: D5.2@3624.01,3391.02 3676.01,3339.02 3676.01,3290 3699.37,3266.64 Q6.3@3744.01,3266.64 3706.62,3229.25 H9.1@3706.62,3197.09
$1N9116: Q6.1 R41.2 | length 208
  Bottom Layer w15: Q6.1@3706.61,3353.36 3706.61,3382.6 3716.01,3392 3828.01,3392 3850.01,3370 R41.2@3850.01,3347.66
$1N10424: D2.2 Q3.1 Q4.3 R17.1 | length 332.2
  Bottom Layer w10: R17.1@3280.01,3934.34 3287.75,3926.6 Q3.1@3350.65,3926.6 3364.79,3926.6 3432.01,3859.38 3432.01,3823.36 3433.37,3822 Q4.3@3435.37,3822 3435.37,3716.8 D2.2@3438.17,3714
$1N10478: Q4.1 R22.1 | length 97.5
  Bottom Layer w10: R22.1@3280.01,3853.66 3348.65,3785.02 Q4.1@3348.65,3784.6
$1N10634: U2.9
$1N10993: H6.3 R26.1 | length 224.1
  Bottom Layer w10: H6.3@3744.53,4148.37 3744.53,4089.47 3844.01,3990 3866.49,3990 R26.1@3867.95,3991.47
$1N10998: H6.4 R27.1 | length 212.6
  Bottom Layer w10: H6.4@3803.59,4148.37 3938.01,4013.96 R27.1@3938.01,3991.47
$1N14735: C22.2 R24.1 SW1.3 | length 303.1
  Top Layer w12: SW1.3@4406.06,3694.95 4504.91,3694.95 R24.1@4600.01,3599.85 4663.71,3599.85 C22.2@4668.01,3595.56
+5V: C3.2 C4.2 C5.2 C6.2 C7.1 C22.1 D1.1 L1.2 R1.2 R4.1 R6.1 R23.2 R24.2 R29.2 R30.2 R32.2 R34.2 R36.2 U2.6 U3.4 USB1.1 | length 3206.8
  Top Layer w10: v2(4428,3469.98) 4575.45,3469.98 4600.01,3494.53 R24.2@4600.01,3540.53 4667.91,3540.53 C22.1@4668.01,3540.44 4670.01,3542.44 4904.63,3542.44 ; USB1.1@4902.81,3231.18 4902.81,3540.61 4904.63,3542.44 ; v2(5234.01,3644) 5234.01,3590 5186.45,3542.44 4904.63,3542.44
  Top Layer w15: L1.2@4140.45,3994 4138.45,3992 v2(4108.72,3992) 4010.01,3893.28 4010.01,3507 v3(4024.01,3493) 4026.01,3495 4114.31,3495 4139.32,3470 v2(4428,3469.98)
  Bottom Layer w10: R4.1@5158.01,3530.34 5174.35,3530.34 v2(5187.74,3543.73) ; R34.2@5234.01,3676.34 v2(5234.01,3644) 5244.01,3634 5352.01,3634 5394.35,3676.34 R32.2@5398.01,3676.34 R30.2@5474.01,3676.34
  Bottom Layer w12: C6.2@4427.57,3588 4444.01,3588 4492.19,3636.19 U2.6@4534.83,3636.19
  Bottom Layer w15: R36.2@3550.01,3347.66 3550.01,3484.44 C3.2@3552.01,3486.44 ; 3920.01,3474 3922.01,3472 R29.2@3922.01,3347.66 ; v2(4108.72,3992) 4272.35,3992 R23.2@4290.35,3974 ; C5.2@4427.56,3522 4428,3521.57 v2(4428,3469.98)
B+: H6.1 H10.1 Q3.2 R17.2 | length 583.2
  Bottom Layer w40: H10.1@3165.01,4117 3177.01,4105 3249.01,4105 3280.01,4074 R17.2@3280.01,3993.66 ; 3288.01,4072 3550.05,4072 H6.1@3626.42,4148.37
BOOT: SW3.1 TP1.1 | length 250.2
  Top Layer w15: TP1.1@3438.01,4112 3535.52,4112 SW3.1@3643.52,4220
DACL: C15.2 C19.2 U2.28 | length 818.3
  Top Layer w10: C15.2@4320.01,3595.56 4326.03,3589.54 4449.37,3589.54 v2(4465.77,3573.13) ; v2@4626.4,3496.83 4641.07,3511.5 v2(4828.17,3511.5)
  Inner1 w10: v2(4465.77,3573.13) 4553.57,3573.13 v2(4628.14,3498.56) ; v2(4828.17,3511.5) 4847.51,3511.5 4922.01,3586 v2(4946.01,3586)
  Bottom Layer w10: U2.28@4739.19,3511.5 v2(4828.17,3511.5) ; C19.2@4921.57,3586 v2(4946.01,3586)
DACR: R3.1 U2.1 | length 566.8
  Top Layer w10: v2(4042.11,3541.01) 4075.53,3541.01 R3.1@4076.01,3540.53
  Inner1 w10: v2(4042.11,3541.01) 4488.01,3541.01 v2(4536.05,3492.97)
  Bottom Layer w10: v2(4536.05,3492.97) 4536.05,3510.72 U2.1@4536.83,3511.5
EC11_A: C23.1 R30.1 SW2.A U2.17 | length 1048.1
  Top Layer w10: v2(5473.95,3771.25) 5521.99,3771.25 SW2.A@5637.97,3655.27
  Inner1 w10: v2(4807.18,3788.57) 4981.21,3788.57 5025.98,3743.8 5446.51,3743.8 v2(5473.95,3771.25)
  Bottom Layer w10: U2.17@4739.19,3786.5 4741.26,3788.57 v2(4807.18,3788.57) ; R30.1@5474.01,3735.66 v2(5473.95,3771.25) C23.1@5473.95,3806.25
EC11_B: C24.1 R32.1 SW2.B U2.16 | length 1021.1
  Top Layer w10: v2(5397.44,3769.91) 5479.66,3852.13 SW2.B@5637.97,3852.13
  Inner1 w10: v2(4785.03,3812.07) 5005.9,3812.07 5048.06,3769.91 v2(5397.44,3769.91)
  Bottom Layer w10: U2.16@4739.19,3811.5 4784.46,3811.5 v2(4785.03,3812.07) ; R32.1@5398.06,3735.71 C24.1@5398.06,3806.25
EC11_D: C25.1 D2.1 D3.1 R34.1 SW2.D | length 2313.7
  Top Layer w10: SW2.D@5008.05,3655.27 5142.25,3655.27 v2(5196.65,3709.67)
  Inner1 w10: v2(3379.49,3715.39) 4016.8,3715.39 4040.55,3691.64 4395.85,3691.64 4450.48,3637.01 5123.99,3637.01 v2(5196.65,3709.67)
  Bottom Layer w10: v2(5196.65,3709.67) 5208.02,3709.67 R34.1@5234.01,3735.66 ; R34.1@5234.06,3735.71 C25.1@5234.06,3806.25
  Bottom Layer w15: D3.1@3345.84,3644 D2.1@3345.84,3714 3378.11,3714 v2(3379.49,3715.39)
EN: R39.1 SW4.1 U5.3 | length 538.8
  Top Layer w15: v2(3492.01,3464) 3501.27,3454.74 U5.3@3501.27,3390.91 ; SW4.1@3559.52,3096 3601.67,3138.15 v2(3601.67,3180.98) R39.1@3601.67,3212
  Inner1 w15: v2(3492.01,3464) 3492.01,3290.64 v2(3601.67,3180.98)
GND: ANT1.1 C1.1 C2.1 C3.1 C4.1 C5.1 C6.1 C7.2 C9.1 C10.1 C11.1 C12.1 C13.2 C16.1 C17.1 C20.1 C23.2 C24.2 C25.2 H4.3 H4.4 H5.1 H6.2 H7.2 H11.1 LED1.1 LED2.1 Q4.2 Q5.2 Q6.2 R2.2 R8.2 R9.2 R13.1 R14.1 R21.1 SW1.1 SW2.C SW2.E SW3.2 SW4.2 U1.2 U2.11 U3.2 U5.9 USB1.5 X1.2 X1.4
  other v1: 3240.01,3040 3414.01,3040 4580.01,3040 4738.01,3040 4814.01,3040 4990.01,3040 5160.01,3040 3666.01,3042 3636.01,3112 5346.01,3114 4580.01,3176 5450.01,3176 3414.01,3182 3790.01,3196 3030.01,3204 3230.01,3210 3966.01,3212 4252.01,3214 3892.01,3228 4470.01,3228 5216.01,3306 5450.01,3306 5560.01,3306 4580.01,3320 4470.01,3322 5716.01,3328 4968.01,3426 5096.01,3426 5216.01,3426 5450.01,3426 5560.01,3426 5716.01,3432 3478.01,3508 5716.01,3536 3592.01,3550 3862.01,3570 4230.01,3572 5306.01,3584 5432.64,3584 5559.27,3584 3314.01,3590 5716.01,3640 3390.01,3646 5560.01,3664 3304.01,3682 5354.01,3720 4896.01,3738 4956.01,3738 5716.01,3744 4042.01,3748 4222.01,3780 3400.01,3782 3580.01,3794 3534.01,3796 5290.01,3796 5559.23,3803.89 5154.01,3812 3380.01,3830 4926.01,3835.06 4122.01,3842 4214.01,3842 5716.01,3848 3660.01,3856 4536.01,3876 5154.01,3878 4706.01,3912 4778.01,3912 4536.01,3914 4422.01,3952 4490.01,3952 4706.01,3952 4808.01,3952 4910.01,3952 5012.01,3952 5114.01,3952 5216.01,3952 5318.01,3952 5420.01,3952 5522.01,3952 5716.01,3952 3994.01,3964 4424.01,4046 5610.01,4046 5708.01,4046 3048.01,4060 3952.01,4096 4180.01,4096 4424.01,4108 3048.01,4128.67 3410.01,4146 3950.01,4146 4114.01,4146 3234.01,4156 3048.01,4197.33 3048.01,4266 3234.01,4268 3466.01,4268 3612.01,4268 3718.01,4268 3820.01,4268 3950.01,4268 4114.01,4268 4266.01,4268 4360.01,4268
KEY_IO: SW1.4 U2.15 | length 204.3
  Top Layer w10: SW1.4@4662.01,3694.99 v2(4662.01,3734)
  Bottom Layer w10: v2(4662.01,3734) 4662.01,3812 4686.51,3836.5 U2.15@4739.19,3836.5
LED_PWM: R31.1 U2.3 | length 403.5
  Bottom Layer w10: R31.1@4298.01,3347.66 4407.67,3347.66 4470.01,3410 4470.01,3540 4491.51,3561.5 U2.3@4536.83,3561.5
LOG_RXD: H7.3 R40.1 U5.15 | length 969.5
  Top Layer w15: R40.1@3154.01,3159.66 3176.01,3181.66 H7.3@3176.01,3284 ; H7.3@3176.01,3290 3196.01,3310 3222.16,3310 3271.02,3358.86 3271.02,3817.02 3414.52,3960.51 3414.52,4003.09 3416.52,4005.09 U5.15@3422.52,4005.09
LOG_TXD: H7.4 R38.1 U5.16 | length 1012.6
  Top Layer w15: R38.1@3072.01,3159.66 3076.01,3163.66 H7.4@3076.01,3284 3143.74,3351.74 3237.01,3351.74 3252.01,3366.74 3252.01,3913.32 U5.16@3343.78,4005.09
MOTOR_PWM: R41.1 U2.2 | length 904.7
  Inner1 w10: v2(3850.01,3260) 4356.01,3260 v2(4472.01,3376)
  Bottom Layer w10: v2(4472.01,3376) 4486.01,3390 4486.01,3518 4504.51,3536.5 U2.2@4536.83,3536.5
  Bottom Layer w15: v2(3850.01,3260) R41.1@3850.01,3288.34
MUSIC_SW: H5.2 R23.1 U2.4 | length 884.4
  Inner1 w14: v2(4381.96,3974) 4382.01,3788 4434.01,3736 v2(4620.01,3736)
  Bottom Layer w14: U2.4@4536.83,3586.5 4578.51,3586.5 4620.01,3628 v2(4620.01,3736)
  Bottom Layer w15: H5.2@4282.6,4144.47 4282.6,4067.41 4349.67,4000.34 R23.1@4349.67,3974 v2(4381.96,3974)
PA0: C19.1 U2.24 | length 137.8
  Bottom Layer w10: U2.24@4739.19,3611.5 4840.95,3611.5 C19.1@4866.45,3586
PA1: C26.2 U2.23 | length 346.9
  Bottom Layer w10: C26.2@4664.01,3351.56 4664.01,3614 4686.51,3636.5 U2.23@4739.19,3636.5
PA2: Q1.2 U2.22 | length 284
  Bottom Layer w10: U2.22@4739.19,3661.5 4932.55,3661.5 Q1.2@4996.65,3597.4
PA3: Q2.3 R5.2 U2.21 | length 363.2
  Bottom Layer w10: U2.21@4739.19,3686.5 4987.15,3686.5 Q2.3@4996.65,3696 4996.65,3791.7 R5.2@4992.35,3796
PA4: U2.20
PC6: U2.26
PC7: R44.1 U2.25 | length 300.2
  Bottom Layer w10: R44.1@4734.01,3353.66 4684.01,3403.66 4684.01,3572 4698.51,3586.5 U2.25@4739.19,3586.5
POWER_ADC: C20.2 R18.1 R21.2 U5.2 | length 243.4
  Top Layer w15: U5.2@3422.52,3390.91 3426.01,3394.41 v2(3426.01,3458)
  Bottom Layer w15: R21.2@3280.01,3482.15 R18.1@3350.01,3482.15 3353.86,3486 C20.2@3424.01,3486 ; C20.2@3424.01,3486.44 3426.01,3484.44 v2(3426.01,3458)
POWER_IO: R22.2 U5.5 | length 654
  Top Layer w15: v2(3312.01,3750) 3386.01,3750 3540.01,3596 3626.01,3596 3658.74,3563.27 U5.5@3658.74,3390.91
  Bottom Layer w15: R22.2@3280.01,3794.34 3312.01,3762.34 v2(3312.01,3750)
POWER_LED: R26.2 U5.13 | length 385.3
  Top Layer w15: U5.13@3580.01,4005.09 3580.01,3936 3616.01,3900 v2(3816.01,3900)
  Bottom Layer w15: v2(3816.01,3900) 3835.81,3900 R26.2@3867.95,3932.15
POWER_SW: D3.2 U5.4 | length 312
  Top Layer w15: v2(3438.01,3610) 3580.01,3468 U5.4@3580.01,3390.91
  Bottom Layer w15: v2(3438.01,3610) 3438.17,3610.16 D3.2@3438.17,3644
RXD: Q2.2 U5.10 | length 1466.8
  Top Layer w10: v2(3816.01,3936) 3816.23,3936.22 U5.10@3816.23,4005.09
  Inner1 w10: v2(3816.01,3936) 4046.35,3705.65 5060.47,3705.65 v2(5083.37,3682.75)
  Bottom Layer w10: Q2.2@5083.37,3658.6 v2@5083.37,3684
SGND: H4.2 R14.2 U2.27 | length 481.2
  Bottom Layer w13: U2.27@4739.19,3536.5 4845.85,3536.5 R14.2@4864.35,3518
  Bottom Layer w15: H4.2@4808.7,3192.64 4864.35,3248.29 R14.2@4864.35,3518
SPK+: H3.1 U4.8 | length 249.1
  Top Layer w20: v2(4066.01,3905.61) U4.8@4097.01,3905.61
  Bottom Layer w20: H3.1@4044.01,4114.63 4044.01,3927.61 v2(4066.01,3905.61)
SPK-: H3.2 R16.2 U4.5 | length 559.3
  Top Layer w20: H3.2@4044.01,4193.37 4044.64,4194 4184.01,4194 4247.01,4131 U4.5@4247.01,3905.61 4247.01,3898.66 R16.2@4316.01,3829.66
SPK_LED: R27.2 R43.2 U5.6 | length 1077.7
  Top Layer w15: v2@3737.49,3318 U5.6@3737.49,3390.91 ; R43.2@3926.01,3143.66 v2(3926.01,3175.45)
  Inner1 w15: v2(3800.01,3674) 3800.01,3378 v2(3738.01,3316) 3878.01,3176 v2@3926.01,3176
  Bottom Layer w15: v2(3800.01,3674) 3800.01,3842 3836.01,3878 3883.86,3878 R27.2@3938.01,3932.15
